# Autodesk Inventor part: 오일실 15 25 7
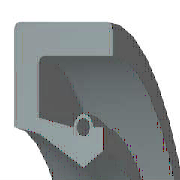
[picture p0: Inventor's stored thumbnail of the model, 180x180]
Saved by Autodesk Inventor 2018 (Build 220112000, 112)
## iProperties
Created: 2012-02
Part Number: 오일실 15 25 7
Material: 고무
Description: 오일 실 - 스프링 장착, 금속 케이스 SM
Document SubType Name: Modeling
Standard: JIS B 2402
Designer: mdu-01
Standards Organization: JIS
Language: ko-KR
Size Designation: 15 25 7 A
Categories: <MemberInstance><Categories><Category DisplayName="샤프트 부품" InternalName="7f7aeb1f-a693-4053-b835-cee3144e0d98" Mnemonic="SHFT"><Category DisplayName="실링" Intern
Density: 0.93 g/cm^3
Appearance: Rubber-Black
IsCustomPart: 1
Author: mdu-01
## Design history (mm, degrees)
body "Solid1"
revolve "회전1" stored, may be unused: angle "d33" = 360 deg
fillet "모깎기1" dims "d34" = 0.35 (= 0.05 x b)
chamfer "모따기1" distance "d35" = 0.7 (= 0.1 x b); stored, may be unused: second distance "d36" = 0.35 (= 0.05 x b), angle "d41" = 45 deg
sketch "스케치2"
  geometry: L1 (8.714, -5.158)-(9.184, -7); L2 (8.214, -4.55)-(8.714, -5.158); L3 (7.5, -1.75)-(8.214, -4.55); L4 (8.167, -0.875)-(7.5, -1.75); L5 (9.284, -0.875)-(8.167, -0.875); L6 (9.284, -1.575)-(9.284, -0.875); L7 (9.284, -5.25)-(9.284, -2.975); L8 (10.5, -5.25)-(9.284, -5.25); L9 (11.5, -1.75)-(10.5, -5.25); L10 (11.5, 0)-(11.5, -1.75); L11 (12.5, 0)-(11.5, 0); L12 (12.5, -7)-(12.5, 0); L13 (9.184, -7)-(12.5, -7); L14 (0, -9.6)-(0, 1.6) reference; L15 (28, 0)-(14, 0) reference; A1 r 0.7 centre (9.284, -2.275) between (9.284, -2.975) and (9.284, -1.575)
  constraints: 26 end point, 4 horizontal, 4 vertical, 2 point on circle, 1 centre point, 1 collinear, 1 parallel
  dimensions: "d2" = 7 distance of L12.start L11.start (= b); "d4" = 0.875 vertical distance of L10.start L5.start (= 0.125 x b); "d6" = 1 distance of L11.start L10.start (= 0.1 x dd - 0.1 x Diam); "d8" = 1.75 distance of L10.start L9.start (= 0.25 x b); "d10" = 1.75 vertical distance of L8.start L1.end (= 0.25 x b); "d12" = 1 horizontal distance of L9.start L8.start (= 0.1 x dd - 0.1 x Diam); "d14" = 0.7 radius of A1 (= 0.1 x b); "d16" = 0 horizontal distance of A1.centre L7.end; "d18" = 0.7 distance of L6.start L5.start (= 0.1 x b); "d20" = 0.66667 horizontal distance of L4.start L3.start (= 0.0666667 x dd - 0.0666667 x Diam); "d22" = 0.1 horizontal distance of L7.start L1.end (= 0.01 x dd - 0.01 x Diam); "d24" = 0.875 vertical distance of L4.start L3.start (= 0.125 x b); "d26" = 2.8 vertical distance of L3.start L2.start (= 0.4 x b); "d28" = 0.71429 horizontal distance of L3.start L2.start (= 0.0714286 x dd - 0.0714286 x Diam); "d30" = 1.84211 vertical distance of L1.start L1.end (= 0.263158 x b); "d32" = 0.5 horizontal distance of L2.start L1.start (= 0.05 x dd - 0.05 x Diam); "d37" = 0 distance between parallel lines of L15 L11; "d38" = 12.5 distance between parallel lines of L14 L12 (= 0.5 x dd); "d39" = 7.5 distance from line of L14 L3.start (= 0.5 x Diam)
other parameters: "dd" = 25 [user parameter; used in 7 equation terms], "Diam" = 15 [user parameter; used in 7 equation terms], "b" = 7 [user parameter; used in 12 equation terms], "d1" = 8 (derived), "d3" = 1 (derived), "d5" = 2 (derived), "d7" = 2 (derived), "d9" = 2 (derived), "d11" = 2 (derived), "d13" = 0.8 (derived), "d15" = 0 (derived), "d17" = 0.8 (derived), "d19" = 1.33333 (derived), "d21" = 0.2 (derived), "d23" = 1 (derived), "d25" = 3.2 (derived), "d27" = 1.42857 (derived), "d29" = 2.10526 (derived), "d31" = 1 (derived), "d40" = 0
